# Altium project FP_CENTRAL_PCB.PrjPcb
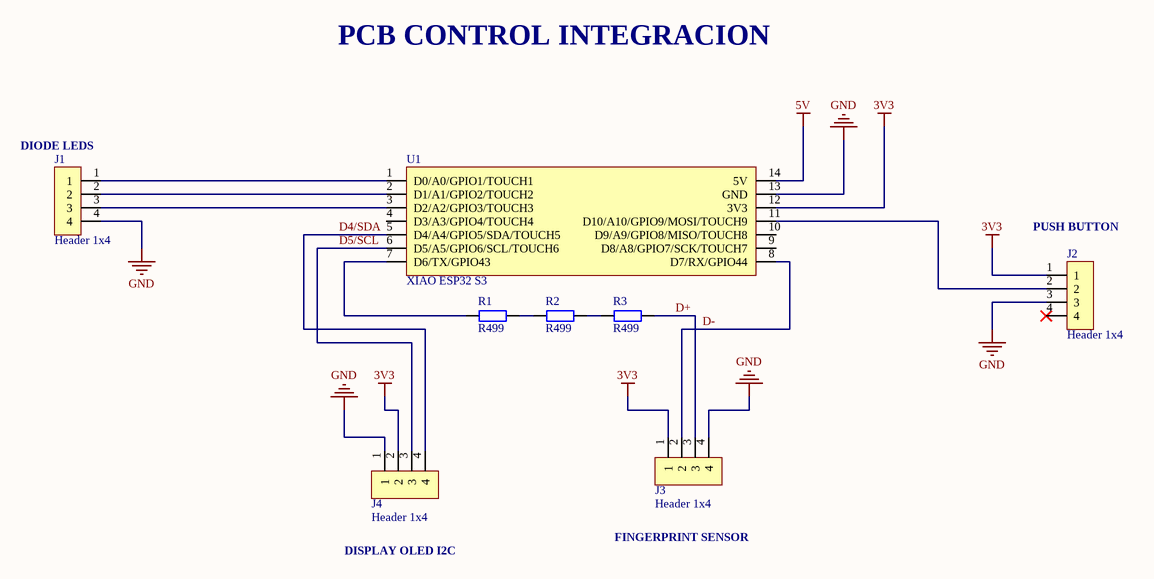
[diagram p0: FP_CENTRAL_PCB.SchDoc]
1 sheet, 8 parts. Net scope: global (net labels, ports and power ports of the same name join across sheets).
Board file: FP_CENTRAL_PCB.PcbDoc

## Sheet FP_CENTRAL_PCB.SchDoc
size A4; SheetNumber: 1; SheetTotal: 1

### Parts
J1  Header 1x4  [HDR4X1_FEMALE]
J2  Header 1x4  [HDR4X1_FEMALE]
J3  Header 1x4  [HDR4X1_FEMALE]
J4  Header 1x4  [HDR4X1_FEMALE]
R1  R499  [RES1206]
R2  R499  [RES1206]
R3  R499  [RES1206]
U1  XIAO ESP32 S3  [XIAO_ESP32_S3_SHIELD]

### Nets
3V3: J2.1 J3.1 J4.2 U1.12(3V3)
5V: U1.14(5V)
GND: J1.4 J2.3 J3.4 J4.1 U1.13(GND)
D4/SDA: J4.4 U1.5(D4/A4/GPIO5/SDA/TOUCH5)
D5/SCL: J4.3 U1.6(D5/A5/GPIO6/SCL/TOUCH6)
D+: J3.3 R3.2
D-: J3.2 U1.8(D7/RX/GPIO44)
NetJ1_1: J1.1 U1.1(D0/A0/GPIO1/TOUCH1)
NetJ1_2: J1.2 U1.2(D1/A1/GPIO2/TOUCH2)
NetJ1_3: J1.3 U1.3(D2/A2/GPIO3/TOUCH3)
NetJ2_2: J2.2 U1.11(D10/A10/GPIO9/MOSI/TOUCH9)
NetR1_1: R1.1 U1.7(D6/TX/GPIO43)
NetR1_2: R1.2 R2.1
NetR2_2: R2.2 R3.1

Not connected (* = marked no-connect by the designer): J2 4*; U1 4(D3/A3/GPIO4/TOUCH4) 9(D8/A8/GPIO7/SCK/TOUCH7) 10(D9/A9/GPIO8/MISO/TOUCH8)

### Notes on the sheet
- PCB CONTROL INTEGRACION
- (near J1) DIODE LEDS
- (near J2) PUSH BUTTON
- DISPLAY OLED I2C
- FINGERPRINT SENSOR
